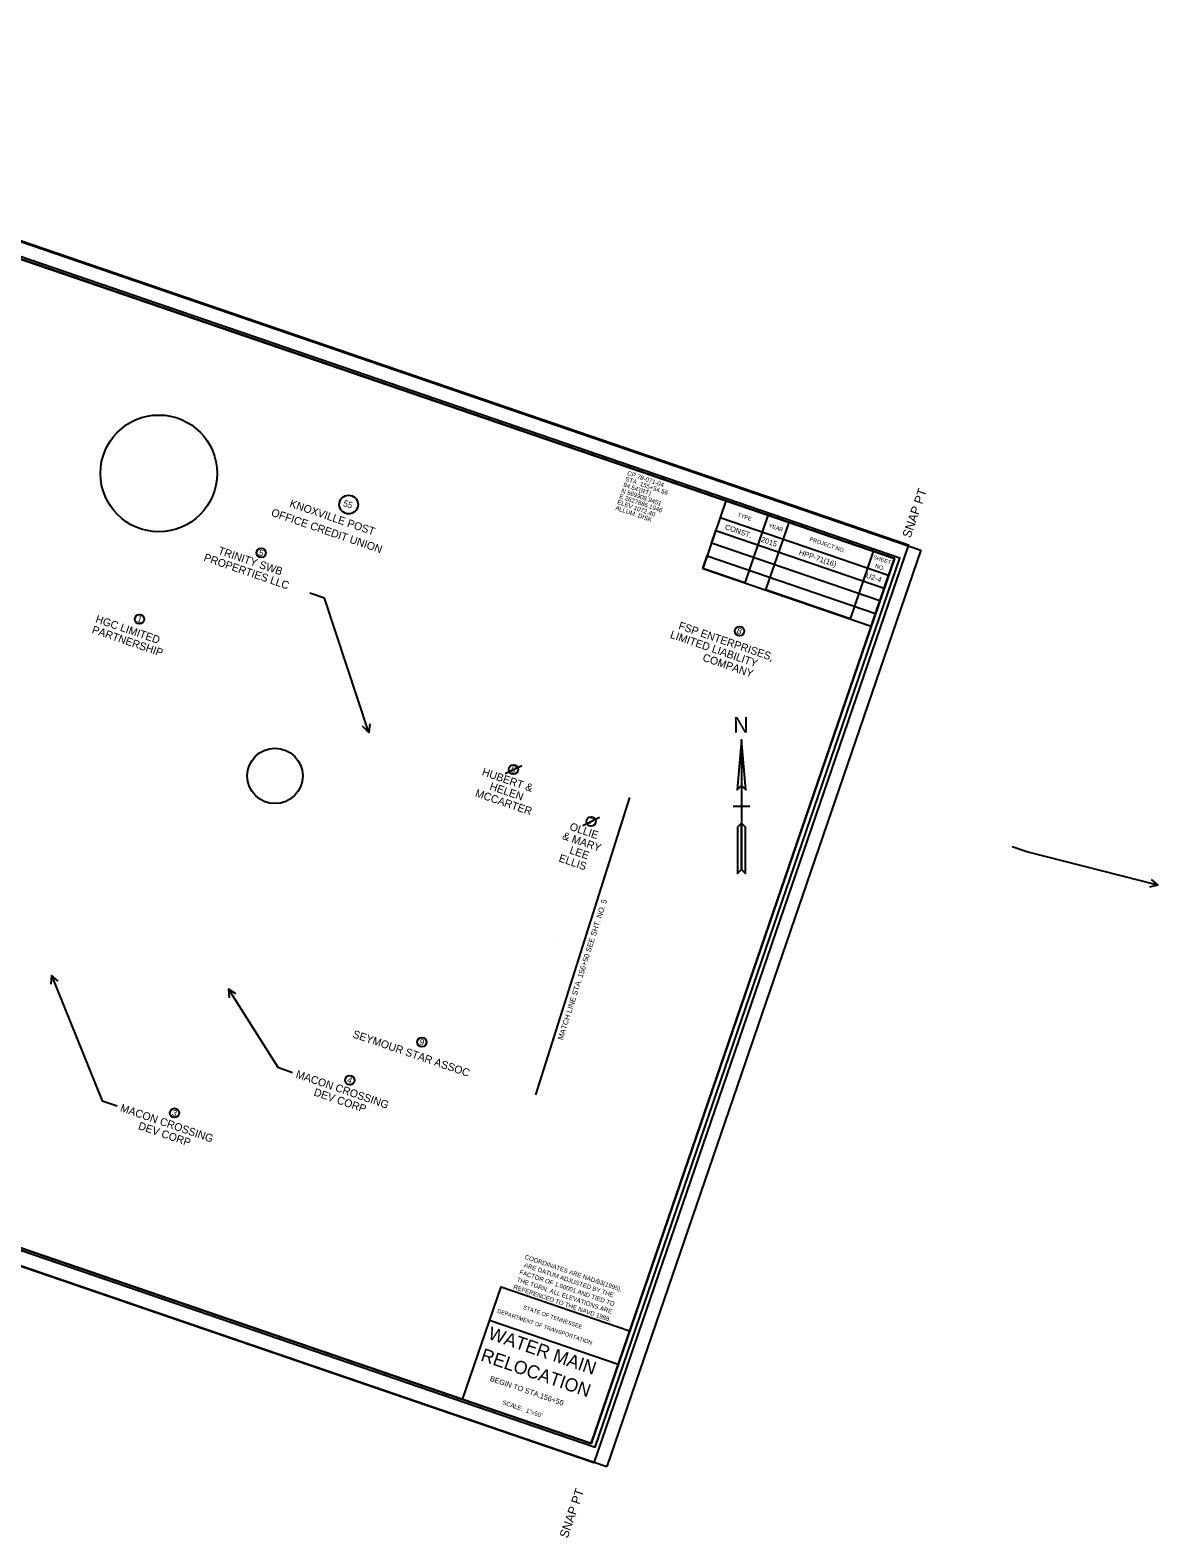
# Model space of a CAD drawing. Extents: x 2626331 to 2628652, y 569305 to 571035.
# Drawn here: x 2627386 to 2628652, y 569305 to 570998 of the extents above; entities that cross this region are included whole.
import ezdxf

# ---------------------------------------------------------------- set-up
doc = ezdxf.new("R2010")
doc.units = 0
for name, color, linetype in [('DESIGN - CENTERLINE - Proposed Text', 7, 'Continuous'), ('DESIGN - SCRATCH - User 1', 7, 'Continuous'), ('DESIGN - SHEET - Corner Text', 7, 'Continuous'), ('DESIGN - SHEET - Light Grid', 7, 'Continuous'), ('DESIGN - SHEET - Linework', 7, 'Continuous'), ('DESIGN - SHEET - Plot Shape', 7, 'Continuous'), ('SURVEY - CONTROL with Text', 7, 'Continuous'), ('SURVEY - GROUND - Top of Rock Layer', 7, 'Continuous'), ('SURVEY - PROPERTY - Owners', 7, 'Continuous'), ('SURVEY - PROPERTY - Tract Numbers', 7, 'Continuous')]:
    doc.layers.add(name, color=color, linetype=linetype)

msp = doc.modelspace()

# ---------------------------------------------------------------- linework, layer by layer
at = {"layer": 'DESIGN - CENTERLINE - Proposed Text'}
for p, q in [((2628184.4, 570126.4), (2628175, 570126.4)), ((2628193.9, 570126.4), (2628184.4, 570126.4))]:
    msp.add_line(p, q, dxfattribs=at)
for points in [[(2628184.4, 570201.4), (2628179.5, 570145.1), (2628184.4, 570150), (2628189.3, 570145.1), (2628184.4, 570201.4), (2628184.4, 570055.9), (2628189, 570051.4), (2628189, 570103.1), (2628184.4, 570107.7), (2628179.9, 570103.1), (2628179.9, 570051.4), (2628184.4, 570055.9)], [(2627953.5, 569802.8), (2628006.4, 569969.6), (2628059.3, 570136.4)]]:
    msp.add_lwpolyline(points, dxfattribs=at)
for points in [[(2628184.4, 570150), (2628189.3, 570145.1), (2628184.4, 570201.4)], [(2628179.9, 570051.4), (2628184.4, 570055.9), (2628184.4, 570107.7), (2628179.9, 570103.1)]]:
    msp.add_lwpolyline(points, close=True, dxfattribs=at)
at = {"layer": 'DESIGN - SCRATCH - User 1'}
for p, q in [((2628181.7, 570435.4), (2628181.7, 570435.4)), ((2628176.8, 570421.2), (2628176.8, 570421.2)), ((2628216.7, 570423.4), (2628216.7, 570423.4)), ((2628172, 570407), (2628172, 570407)), ((2628207, 570395), (2628207, 570395)), ((2628211.8, 570409.2), (2628211.8, 570409.2)), ((2628275.8, 570403.1), (2628275.8, 570403.1)), ((2628167.1, 570392.8), (2628167.1, 570392.8)), ((2628202.1, 570380.8), (2628202.1, 570380.8)), ((2628270.9, 570388.9), (2628270.9, 570388.9)), ((2628334.9, 570382.9), (2628334.9, 570382.9)), ((2628266.1, 570374.8), (2628266.1, 570374.8)), ((2628330.1, 570368.7), (2628330.1, 570368.7)), ((2628261.2, 570360.6), (2628261.2, 570360.6)), ((2628325.2, 570354.5), (2628325.2, 570354.5)), ((2628320.3, 570340.3), (2628320.3, 570340.3)), ((2627973.8, 569980.7), (2627973.8, 569980.7)), ((2627958.7, 569480.4), (2627958.7, 569480.4))]:
    msp.add_line(p, q, dxfattribs=at)
at = {"layer": 'DESIGN - SHEET - Light Grid'}
msp.add_lwpolyline([(2626445.3, 569947.1), (2628020.3, 569407.2), (2628362.4, 570405.2), (2626787.4, 570945.1)], close=True, dxfattribs=at)
at = {"layer": 'DESIGN - SHEET - Linework'}
for p, q in [((2626683.1, 570997.9), (2628385.9, 570414.3)), ((2628385.9, 570414.3), (2628033.2, 569385.6)), ((2626330.5, 569969.3), (2628033.2, 569385.6))]:
    msp.add_line(p, q, dxfattribs=at)
for points in [[(2626867, 570915.1), (2626526.5, 569921.9), (2628015.7, 569411.4), (2628356.1, 570404.7), (2626867, 570915.1)], [(2628166.9, 570469.5), (2628141, 570393.8), (2628330.2, 570329), (2628356.1, 570404.7), (2628332.5, 570412.8), (2628306.5, 570337.1), (2628212, 570369.5), (2628237.9, 570445.2), (2628214.2, 570453.3), (2628188.3, 570377.6), (2628141, 570393.8), (2628145.9, 570408), (2628335.1, 570343.2), (2628339.9, 570357.4), (2628150.7, 570422.2), (2628155.6, 570436.4), (2628344.8, 570371.6), (2628349.7, 570385.7), (2628160.5, 570450.6)], [(2627871.4, 569460.9), (2627914.7, 569587.3), (2628059, 569537.8), (2628046, 569500), (2627901.8, 569549.4)]]:
    msp.add_lwpolyline(points, dxfattribs=at)
at = {"layer": 'DESIGN - SHEET - Plot Shape'}
for points in [[(2626763.7, 570971.4), (2628371.8, 570420.1), (2628018.6, 569389.6), (2626410.4, 569940.8)], [(2626786.5, 570942.7), (2628356.1, 570404.7), (2628015.7, 569411.4), (2626446.1, 569949.5)]]:
    msp.add_lwpolyline(points, close=True, dxfattribs=at)
at = {"layer": 'SURVEY - CONTROL with Text'}
msp.add_circle((2627530.5, 570500.4), 65.5, dxfattribs=at)
at = {"layer": 'SURVEY - GROUND - Top of Rock Layer'}
msp.add_circle((2627660.9, 570160.8), 31.1, dxfattribs=at)
at = {"layer": 'SURVEY - PROPERTY - Tract Numbers'}
for p, q in [((2627919.2, 570163.4), (2627938.1, 570172.6)), ((2628006.3, 570105.1), (2628025.1, 570114.4))]:
    msp.add_line(p, q, dxfattribs=at)
for points in [[(2627716.4, 570360.5), (2627699.9, 570366.1)], [(2627766.1, 570209.6), (2627716.4, 570360.5)], [(2627767.5, 570219.3), (2627766.1, 570209.6), (2627759.2, 570216.5)], [(2628504.8, 570075.4), (2628488.2, 570081.1)], [(2628651.8, 570038), (2628504.8, 570075.4)], [(2628644.4, 570044.4), (2628651.8, 570038), (2628642.3, 570035.9)], [(2627417.4, 569930.4), (2627410.1, 569936.9), (2627409.3, 569927.1)], [(2627410.1, 569936.9), (2627467, 569796)], [(2627608.6, 569921.3), (2627664, 569833.7)], [(2627617, 569916.3), (2627608.6, 569921.3), (2627609.6, 569911.6)], [(2627664, 569833.7), (2627680.5, 569828)], [(2627467, 569796), (2627483.6, 569790.3)]]:
    msp.add_lwpolyline(points, dxfattribs=at)
for centre, radius in [((2627743.6, 570465.4), 10.5), ((2627645.5, 570411.2), 5.25), ((2627508.7, 570336.6), 5.25), ((2628182.3, 570323.4), 5.25), ((2627928.6, 570168), 5.25), ((2628015.7, 570109.7), 5.25), ((2627825.8, 569861.9), 5.25), ((2627744.8, 569819.2), 5.25), ((2627548.1, 569782.4), 5.25)]:
    msp.add_circle(centre, radius, dxfattribs=at)

# ---------------------------------------------------------------- texts
at = {"layer": 'DESIGN - CENTERLINE - Proposed Text'}
msp.add_text('N', height=17.7, dxfattribs=at).set_placement((2628175.4, 570209.4))
msp.add_text('MATCH LINE STA. 156+50 SEE SHT. NO. 5', height=6, rotation=72.3958, dxfattribs=at).set_placement((2627983.8, 569863.8))
at = {"layer": 'DESIGN - SHEET - Corner Text'}
for s, height, rotation, p in [('  SNAP PT', 10, 71.0785, (2628371.8, 570420.1)), ('TYPE', 4.5, 341.0785, (2628179.7, 570452.2)), ('CONST.', 6, 341.0785, (2628165.4, 570437.8)), ('2015', 6, 341.0785, (2628205.9, 570423.9)), ('YEAR', 4.5, 341.0785, (2628214.5, 570440.1)), ('PROJECT NO.', 4.5, 341.0785, (2628260.5, 570424.8)), ('HPP-71(16)', 6, 341.0785, (2628248.5, 570409.3)), ('SHEET', 4.5, 341.0785, (2628332, 570404.7)), ('NO.', 4.5, 341.0785, (2628334, 570394.8)), ('U2-4', 6, 341.0785, (2628323.6, 570383.6)), ('COORDINATES ARE NAD/83(1995),', 5, 341.0785, (2627940.8, 569618.9)), ('FACTOR OF 1.00001 AND TIED TO', 5, 341.0785, (2627934.8, 569601.9)), ('ARE DATUM ADJUSTED BY THE', 5, 341.0785, (2627940, 569609.7)), ('REFERENCED TO THE NAVD 1988.', 5, 341.0785, (2627928.1, 569585.2)), ('THE TGRN. ALL ELEVATIONS ARE', 5, 341.0785, (2627931.8, 569593.4)), ('STATE OF TENNESSEE', 4.5, 341.0785, (2627939, 569562.5)), ('DEPARTMENT OF TRANSPORTATION', 4.5, 341.0785, (2627910, 569558.4)), ('WATER MAIN', 14.76, 341.0785, (2627899.1, 569529.1)), ('RELOCATION', 14.76, 341.0785, (2627890.8, 569504.7)), ('BEGIN TO STA.156+50', 5.905, 341.0785, (2627901.6, 569481.9)), ('SCALE:  1"=50\'', 4.921, 341.0785, (2627915.6, 569455.5)), ('SNAP PT  ', 10, 71.0785, (2627989.4, 569304.4))]:
    msp.add_text(s, height=height, rotation=rotation, dxfattribs=at).set_placement(p)
at = {"layer": 'SURVEY - CONTROL with Text'}
for s, p in [('CP 78-071-04', (2628055.8, 570498.7)), ('N 569908.9451', (2628049.1, 570479.2)), ("94.54'(RT)", (2628051.3, 570485.7)), ('STA. 155+54.56', (2628053.6, 570492.2)), ('ALLUM. DISK', (2628042.4, 570459.7)), ('ELEV 1072.40', (2628044.7, 570466.2)), ('E 2627886.1946', (2628046.9, 570472.7))]:
    msp.add_text(s, height=5, rotation=341.0785, dxfattribs=at).set_placement(p)
at = {"layer": 'SURVEY - PROPERTY - Owners'}
for s, p in [('KNOXVILLE POST ', (2627676.6, 570463.1)), ('OFFICE CREDIT UNION', (2627655.9, 570453)), ('TRINITY SWB', (2627596.3, 570410.2)), ('PROPERTIES LLC', (2627580.2, 570402.5)), ('PARTNERSHIP', (2627454.7, 570321.5)), ('HGC LIMITED', (2627458.7, 570333.3)), ('FSP ENTERPRISES,', (2628113.1, 570325.9)), ('LIMITED LIABILITY', (2628103.7, 570315.9)), ('COMPANY', (2628140.1, 570290.2)), ('HUBERT &', (2627892.5, 570161.8)), ('MCCARTER', (2627884.9, 570138)), ('HELEN', (2627901.1, 570145.6)), ('OLLIE', (2627990.8, 570100.4)), ('& MARY', (2627982.7, 570090)), ('LEE', (2627990.8, 570074)), ('ELLIS', (2627978.7, 570065)), ('SEYMOUR STAR ASSOC', (2627747.3, 569867.5)), ('MACON CROSSING', (2627683.5, 569822.4)), ('DEV CORP', (2627703.7, 569802.3)), ('MACON CROSSING', (2627486.5, 569784.6)), ('DEV CORP', (2627506.7, 569764.5))]:
    msp.add_text(s, height=8.75, rotation=341.0785, dxfattribs=at).set_placement(p)
at = {"layer": 'SURVEY - PROPERTY - Tract Numbers'}
for s, p in [('55', (2627736.8, 570464.1)), ('5', (2627641.9, 570408.7)), ('1', (2627505.4, 570334.1)), ('8', (2628178.6, 570321)), ('6', (2627924.9, 570165.6)), ('7', (2628012.1, 570107.3)), ('9', (2627822.2, 569859.5)), ('4', (2627741.2, 569816.8)), ('3', (2627544.5, 569779.9))]:
    msp.add_text(s, height=7, rotation=341.0785, dxfattribs=at).set_placement(p)

doc.saveas('drawing.dxf')
